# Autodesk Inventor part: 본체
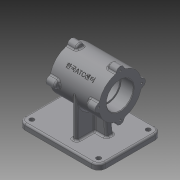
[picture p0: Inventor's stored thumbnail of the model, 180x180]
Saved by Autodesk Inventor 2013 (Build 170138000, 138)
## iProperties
Created: 2015-12
Part Number: 본체
Material: 일반
Document SubType Name: Modeling
Designer: cad8
Density: 1 g/cm^3
Author: cad8
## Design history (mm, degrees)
sketch "스케치1"
  geometry: L1 (-70, 55)-(70, 55); L2 (70, 55)-(70, -55); L3 (70, -55)-(-70, -55); L4 (-70, -55)-(-70, 55); 3 further points
  constraints: 8 end point, 2 midpoint, 2 parallel, 1 horizontal, 1 horizontal alignment, 1 perpendicular, 1 vertical alignment
  dimensions: "d0" = 140 distance of L1.start L1.end; "d2" = 110 distance of L1.end L2.end
extrude "돌출1" new body sketch "스케치1" distance "d3" = 10; taper "d4" = 0 deg
node "작업 평면1"
sketch "스케치2"
  geometry: L1 (0, 110)-(0, 0) reference; C1 r 37 at (80, 55); 1 further point
  constraints: 1 centre point, 1 horizontal alignment
  dimensions: "d6" = 74 diameter of C1; "d8" = 80 distance from line of L1 C1.centre
extrude "돌출2" join sketch "스케치2" distance "d9" = 85; taper "d10" = 0 deg
node "작업 평면2"
sketch "스케치3"
  geometry: L1 (0, 110)-(10, 110) reference; L2 (10, 110)-(10, 0) reference; L3 (10, 0)-(0, 0) reference; L4 (0, 0)-(0, 110) reference; L5 (0, 92)-(80, 92); L6 (80, 92)-(80, 18); L7 (80, 18)-(0, 18); L8 (0, 18)-(0, 92); C1 r 37 at (80, 55) reference; 1 further point
  constraints: 8 end point, 2 parallel, 2 tangent, 1 horizontal, 1 midpoint, 1 perpendicular, 1 point on line
extrude "돌출3" join sketch "스케치3" stored distance "d12" = 8; taper "d13" = 0 deg
node "작업 평면3"
hole "구멍1" diameter "d20" = 47; stored, may be unused: countersink angle "d24" = 90 deg, drill point angle "d26" = 0 deg; dims "d18" = 10, "d19" = 10, "d21" = 6, "d22" = 47, "d23" = 22, "d25" = 22
hole "구멍2" diameter "d29" = 42; stored, may be unused: countersink angle "d33" = 90 deg, drill point angle "d35" = 0 deg; dims "d27" = 10, "d28" = 10, "d30" = 6, "d31" = 47, "d32" = 22, "d34" = 41
hole "구멍3" diameter "d38" = 47; stored, may be unused: countersink angle "d42" = 90 deg, drill point angle "d44" = 0 deg; dims "d36" = 10, "d37" = 10, "d39" = 6, "d40" = 47, "d41" = 22, "d43" = 22
sketch "스케치5"
  geometry: L1 (-6, 10)-(70, 10) reference; L2 (70, 10)-(70, 0) reference; L3 (70, 0)-(-70, 0) reference; L4 (-70, 0)-(-70, 10) reference; L5 (-70, 10)-(-14, 10) reference; L6 (32.5, 43)-(-6, 43) reference; L7 (32.5, 56.5)-(32.5, 43) reference; L8 (32.5, 103.5)-(10.5, 103.5) reference; L9 (10.5, 103.5)-(10.5, 101) reference; L10 (10.5, 101)-(-30.5, 101) reference; L11 (-30.5, 101)-(-30.5, 103.5) reference; L12 (-30.5, 103.5)-(-52.5, 103.5) reference; L13 (-52.5, 43)-(-52.5, 56.5) reference; L14 (-14, 43)-(-52.5, 43) reference; L15 (-52.5, 117)-(32.5, 117) reference; L16 (32.5, 117)-(32.5, 103.5) reference; L17 (10.5, 56.5)-(32.5, 56.5) reference; L18 (10.5, 59)-(10.5, 56.5) reference; L19 (-30.5, 59)-(10.5, 59) reference; L20 (-30.5, 56.5)-(-30.5, 59) reference; L21 (-52.5, 56.5)-(-30.5, 56.5) reference; L22 (-52.5, 103.5)-(-52.5, 117) reference; L23 (-52.5, 117)-(-52.5, 124); L24 (-52.5, 124)-(-37.5, 124); L25 (-37.5, 124)-(-34.952, 117); L26 (-14, 10)-(-14, 43) reference; L27 (-6, 43)-(-6, 10) reference; 1 further point
  constraints: 6 end point, 1 collinear, 1 perpendicular, 1 point on line
  dimensions: "d45" = 110 deg angle of L15 L25; "d46" = 15 distance of L23.end L24.end; "d48" = 7 distance of L15.start L23.end
revolve "회전1" sketch "스케치5" stored, may be unused: angle "d49" = 90 deg
fillet "모깎기1" dims "d50" = 3
fillet "모깎기2" dims "d51" = 3
node "작업 평면4"
sketch "스케치6"
  geometry: A1 r 7 centre (-117, 55) between (-118.239, 61.889) and (-118.239, 48.111) reference; 2 further points
  constraints: 1 coincident
hole "구멍4" sketch "스케치6" at (-117, 55) diameter "d55" = 3.242; stored, may be unused: countersink angle "d59" = 90 deg, drill point angle "d61" = 118 deg; dims "d56" = 8, "d57" = 47, "d58" = 22, "d60" = 11
node "작업 평면5"
node "작업 평면8"
  node "작업 평면7"
sketch "스케치7"
  geometry: L1 (0, -18.921)-(0, 18.921) reference; 3 further points
  constraints: 1 horizontal alignment, 1 midpoint, 1 other
  dimensions: "d67" = 42.5 distance from line of point (42.5, 0) L1
feature "엠보싱1" sketch "스케치7" dims "d68" = 0.5, "d69" = 0
fillet "모깎기3" dims "d70" = 12
hole "구멍5" diameter "d73" = 8; stored, may be unused: countersink angle "d77" = 90 deg, drill point angle "d79" = 118 deg; dims "d71" = 10, "d72" = 10, "d74" = 8, "d75" = 47, "d76" = 22, "d78" = 11
node "작업 평면9"
fillet "모깎기8" dims "d96" = 3
fillet "모깎기9" dims "d97" = 0.3
chamfer "모따기1" distance "d98" = 1; stored, may be unused: second distance "d99" = 2, angle "d100" = 45 deg
sketch "스케치9"
  geometry: L1 (-40.526, 43)-(-41.5, 44.621) reference; L2 (-41.5, 44.621)-(-52.5, 44.621) reference; L3 (-52.5, 44.621)-(-52.5, 55.5) reference; L4 (-52.5, 55.5)-(-51.5, 56.5) reference; L5 (-51.5, 56.5)-(-30.8, 56.5) reference; L6 (-30.5, 56.8)-(-30.5, 59) reference; L7 (-30.5, 59)-(10.5, 59) reference; L8 (10.5, 59)-(10.5, 56.8) reference; L9 (10.8, 56.5)-(31.5, 56.5) reference; L10 (31.5, 56.5)-(32.5, 55.5) reference; L11 (32.5, 55.5)-(32.5, 44.621) reference; L12 (32.5, 44.621)-(21.5, 44.621) reference; L13 (21.5, 44.621)-(20.526, 43) reference; L14 (20.526, 43)-(21.5, 41.379) reference; L15 (21.5, 41.379)-(32.5, 41.379) reference; L16 (32.5, 41.379)-(32.5, 36) reference; L17 (32.5, 36)-(19.601, 36) reference; L18 (16.782, 37.974)-(15.671, 41.026) reference; L19 (12.852, 43)-(-6, 43) reference; L20 (-6, 43)-(-6, 10) reference; L21 (-6, 10)-(67, 10) reference; L22 (70, 7)-(70, 0) reference; L23 (70, 0)-(-70, 0) reference; L24 (-70, 0)-(-70, 7) reference; L25 (-67, 10)-(-14, 10) reference; L26 (-14, 10)-(-14, 43) reference; L27 (-14, 43)-(-32.852, 43) reference; L28 (-35.671, 41.026)-(-36.782, 37.974) reference; L29 (-39.601, 36)-(-52.5, 36) reference; L30 (-52.5, 36)-(-52.5, 41.379) reference; L31 (-52.5, 41.379)-(-41.5, 41.379) reference; L32 (-41.5, 41.379)-(-40.526, 43) reference; L33 (-41.5, 115.379)-(-40.526, 117) reference; L34 (-40.526, 117)-(-41.5, 118.621) reference; L35 (-41.5, 118.621)-(-52.5, 118.621) reference; L36 (-52.5, 118.621)-(-52.5, 124) reference; L37 (-52.5, 124)-(-39.601, 124) reference; L38 (-36.782, 122.026)-(-35.671, 118.974) reference; L39 (-32.852, 117)-(12.852, 117) reference; L40 (15.671, 118.974)-(16.782, 122.026) reference; L41 (19.601, 124)-(32.5, 124) reference; L42 (32.5, 124)-(32.5, 118.621) reference; L43 (32.5, 118.621)-(21.5, 118.621) reference; L44 (21.5, 118.621)-(20.526, 117) reference; L45 (20.526, 117)-(21.5, 115.379) reference; L46 (21.5, 115.379)-(32.5, 115.379) reference; L47 (32.5, 115.379)-(32.5, 104.5) reference; L48 (32.5, 104.5)-(31.5, 103.5) reference; L49 (31.5, 103.5)-(10.8, 103.5) reference; L50 (10.5, 103.2)-(10.5, 101) reference; L51 (10.5, 101)-(-30.5, 101) reference; L52 (-30.5, 101)-(-30.5, 103.2) reference; L53 (-30.8, 103.5)-(-51.5, 103.5) reference; L54 (-51.5, 103.5)-(-52.5, 104.5) reference; L55 (-52.5, 104.5)-(-52.5, 115.379) reference; L56 (-52.5, 115.379)-(-41.5, 115.379) reference; L57 (15, 10)-(10.48, 46.815); L58 (10.48, 46.815)-(-10, 46.815); L59 (-10, 46.815)-(-10, 10); L60 (-10, 10)-(15, 10); A1 r 0.3 centre (-30.8, 56.8) between (-30.8, 56.5) and (-30.5, 56.8) reference; A2 r 0.3 centre (10.8, 56.8) between (10.5, 56.8) and (10.8, 56.5) reference; A3 r 3 centre (19.601, 39) between (16.782, 37.974) and (19.601, 36) reference; A4 r 3 centre (67, 7) between (70, 7) and (67, 10) reference; A5 r 3 centre (-67, 7) between (-67, 10) and (-70, 7) reference; A6 r 3 centre (-39.601, 39) between (-39.601, 36) and (-36.782, 37.974) reference; A7 r 3 centre (-39.601, 121) between (-36.782, 122.026) and (-39.601, 124) reference; A8 r 3 centre (19.601, 121) between (19.601, 124) and (16.782, 122.026) reference; A9 r 0.3 centre (10.8, 103.2) between (10.8, 103.5) and (10.5, 103.2) reference; A10 r 0.3 centre (-30.8, 103.2) between (-30.5, 103.2) and (-30.8, 103.5) reference; 2 further points
  constraints: 8 end point, 1 collinear, 1 midpoint, 1 parallel, 1 perpendicular, 1 point on line, 1 vertical alignment, 4 other
  dimensions: "d101" = 97 deg angle of L60 L57; "d102" = 25 horizontal distance of point (-10, 117) L57.start; "d104" = 20.47966 distance of L57.end L58.end
extrude "돌출6" join sketch "스케치9" stored distance "d105" = 12; taper "d106" = 0 deg
node "작업 평면10"
fillet "모깎기10" dims "d107" = 3
fillet "모깎기11" dims "d108" = 3
fillet "모깎기12" dims "d109" = 3
fillet "모깎기13" dims "d110" = 3
fillet "모깎기14" dims "d111" = 3
fillet "모깎기15" dims "d112" = 3
node "솔리드1"
pattern_circular "원형 패턴1" dims "d53" = 360 deg
mirror "대칭2"
pattern_circular "원형 패턴2" dims angle "d63" = 360 deg
mirror "대칭3"
pattern_linear "직사각형 패턴1" dims "d82" = 86
pattern_linear "직사각형 패턴2" dims "d85" = 116
mirror "대칭5"
node "작업축1"
node "작업 평면6"
node "절단 모서리 투영1"
node "절단 모서리 투영4"
node "절단 모서리 투영6"
other parameters: "d5" = -37.5, "d66" = -45 deg
